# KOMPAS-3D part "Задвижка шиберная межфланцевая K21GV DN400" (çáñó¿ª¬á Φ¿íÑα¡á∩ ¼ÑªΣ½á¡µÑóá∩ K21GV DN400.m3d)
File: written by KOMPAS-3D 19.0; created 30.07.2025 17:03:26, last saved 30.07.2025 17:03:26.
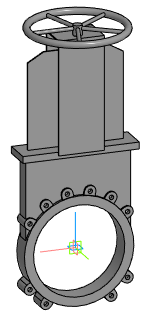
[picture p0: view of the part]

Document properties: Автор: Евгений; Полное имя файла: E:\Dendor Работа Сачек\3D для проектировщиков\2.3 Тип K21GV. Задвижка шиберная межфланцевая\stp_Задвижка шиберная K21GV DN50-400 с маховиком\Задвижка шиберная межфланцевая K21GV DN400.m3d

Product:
- Part/product: Задвижка шиберная межфланцевая K21GV DN400

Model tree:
1. Операция без истории:1  (labels: Задвижка шиберная межфланцевая K21GV DN400)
